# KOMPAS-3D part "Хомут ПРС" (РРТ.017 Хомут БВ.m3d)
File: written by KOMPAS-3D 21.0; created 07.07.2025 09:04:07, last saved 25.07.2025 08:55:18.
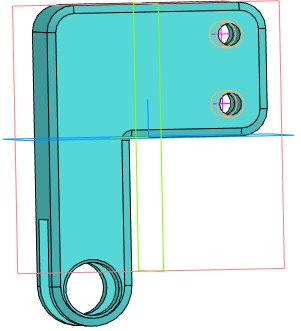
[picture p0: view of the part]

Document properties: Полное имя файла: C:\Users\User\Desktop\Ручной ротатор КД\Модели КД\РРТ.017 Хомут БВ.m3d; Автор: User

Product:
- Part/product: Хомут ПРС
    Масса: 0.239858
    Форматы листов документа: A4
  - Body: Тело 1
      Масса: 0.239922

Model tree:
1. Эскиз:1
2. Элемент выдавливания:1
     Расстояние 1 = 25
3. Эскиз:2  (with: Элемент выдавливания:1)
4. Элемент выдавливания:2
     Расстояние 1 = 35
5. Скругление:5  (with: Элемент выдавливания:2)
     Радиус = 0.4
6. Эскиз:3  (with: Элемент выдавливания:1)
7. Элемент выдавливания:3
     Расстояние 2 = 22
8. Эскиз:4
9. Элемент выдавливания:4
     Расстояние 1 = 17; Расстояние 2 = 17
10. Скругление:6  (with: Элемент выдавливания:2)
     Радиус = 7.5
11. Скругление:7  (with: Элемент выдавливания:1)
     Радиус = 5
12. Фаска:2  (with: Элемент выдавливания:1, Скругление:7, Скругление:6, Элемент выдавливания:2, Скругление:5)
     Угол = 45; Длина 1 = 1.5; Длина 2 = 1.5
13. Эскиз:5
14. Отверстие:1  (with: Элемент выдавливания:1, Фаска:2)
     Глубина выреза = 18; Диаметр отверстия = 5; Угол конуса дна = 118; Расстояние 1 = -32.5; Расстояние 2 = -4.5; Диаметр цековки = 8; Глубина цековки = 6
15. M5  (with: Элемент выдавливания:1)  (labels: M5; cil0_24705-2004 coarse)
     Длина резьбы = 27; Шаг резьбы = 0.8; Номинальный диаметр резьбы = 5
16. Отверстие:2  (with: Элемент выдавливания:1, Фаска:2, M5)  (labels: M5; cil0_24705-2004 coarse)
     Глубина выреза = 18; Диаметр отверстия = 5; Угол конуса дна = 118; Расстояние 1 = -17.5; Расстояние 2 = -5.5; Диаметр цековки = 8; Глубина цековки = 6; Длина резьбы = 27; Шаг резьбы = 0.8; Номинальный диаметр резьбы = 5
17. Элемент выдавливания:6  (with: Элемент выдавливания:2)
     Расстояние 2 = 62
18. Эскиз:6  (with: Элемент выдавливания:1)
19. Элемент выдавливания:7
     Расстояние 1 = 35
20. Эскиз:7  (with: Элемент выдавливания:1, Элемент выдавливания:7)
21. Элемент выдавливания:8
     Расстояние 1 = 15
22. Отверстие:3  (with: Элемент выдавливания:1, M5)  (labels: M5; cil0_24705-2004 coarse)
     Глубина выреза = 15; Диаметр отверстия = 4.13397; Угол конуса дна = 118; Расстояние 1 = -7; Расстояние 2 = 19; Длина резьбы = 14; Шаг резьбы = 0.8; Номинальный диаметр резьбы = 5
23. Отверстие:4  (with: Элемент выдавливания:1, M5)  (labels: M5; cil0_24705-2004 coarse)
     Глубина выреза = 15; Диаметр отверстия = 4.13397; Угол конуса дна = 118; Расстояние 1 = -7; Расстояние 2 = 6; Длина резьбы = 14; Шаг резьбы = 0.8; Номинальный диаметр резьбы = 5
24. Фаска:3  (with: Элемент выдавливания:4)
     Угол = 45; Длина 1 = 0.5; Длина 2 = 0.5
